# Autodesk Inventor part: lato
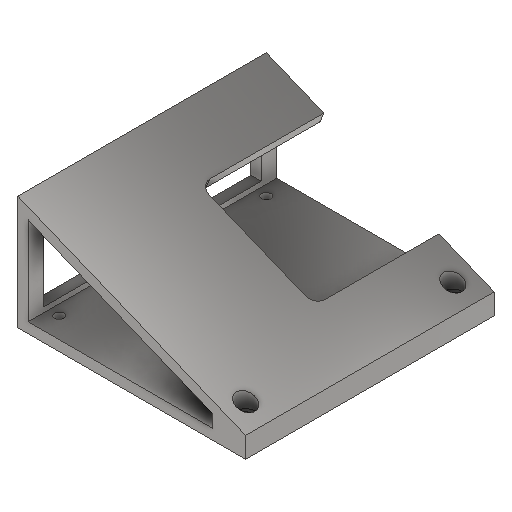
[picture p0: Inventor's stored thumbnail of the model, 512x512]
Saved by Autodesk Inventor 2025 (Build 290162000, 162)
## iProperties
Created: 2025-05
Part Number: lato
Material: Plastica PET
Document SubType Name: Modeling
Designer: R5800u
Density: 1.541 g/cm^3
Appearance: Acciaio - Lucido
Author: R5800u
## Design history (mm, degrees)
sketch "Schizzo1"
  geometry: L1 (0, 0)-(190, 0) reference; L2 (190, 0)-(190, 5) reference; L3 (0, 5)-(190, 5) reference; L4 (0, 0)-(0, 5) reference; L5 (300, -50)-(300, -55) reference; L6 (300, -50)-(300, -40); L7 (300, -40)-(190, 5); L8 (190, 5)-(190, -50); L9 (190, -50)-(300, -50); L10 (195, -2.448)-(295, -43.357); L11 (295, -43.357)-(295, -45); L12 (295, -45)-(195, -45); L13 (195, -45)-(195, -2.448); L14 (284, -38.857)-(284, -45); 1 further point
  constraints: 18 end point, 3 point on line, 2 perpendicular, 1 vertical, 3 other
  dimensions: "d0" = 10 distance of L5.start L6.end; "d1" = 5 distance between parallel lines of L7 L10; "d2" = 16 distance between parallel lines of L6 L14
extrude "Estrusione1" new body sketch "Schizzo1" distance "d3" = 120; taper "d4" = 0 deg
sketch "Schizzo2"
  geometry: L1 (0, 55)-(0, 0) reference; L2 (0, 55)-(-120, 55) reference; L3 (-120, 0)-(-120, 55) reference; L4 (0, 0)-(-120, 0) reference; L5 (-112.5, 47.5)-(-7.5, 47.5); L6 (-7.5, 47.5)-(-7.5, 7.5); L7 (-7.5, 7.5)-(-112.5, 7.5); L8 (-112.5, 7.5)-(-112.5, 47.5); 1 further point
  constraints: 8 end point, 3 other
  dimensions: "d5" = 7.5 distance between parallel lines of L2 L5
extrude "Estrusione2" cut sketch "Schizzo2" stored distance "d6" = 10; taper "d7" = 0 deg
sketch "Schizzo3"
  geometry: L1 (81.5, -69.5)-(81.5, -61.5) reference; L2 (93.5, -69.5)-(81.5, -69.5) reference; L3 (93.5, -61.5)-(93.5, -69.5) reference; L4 (81.5, -61.5)-(93.5, -61.5) reference; L5 (93.5, 61.5)-(81.5, 61.5) reference; L6 (81.5, 61.5)-(81.5, 69.5) reference; L7 (81.5, 69.5)-(93.5, 69.5) reference; 1 further point
  constraints: 14 end point, 4 horizontal, 3 vertical, 8 other
extrude "Estrusione3" cut sketch "Schizzo3" distance "d8" = 10; taper "d9" = 0 deg
sketch "Schizzo4"
  geometry: L1 (110, -107.9)-(110, -112.1) reference; L2 (110, -110)-(100, -110); L3 (0, -120)-(110, -120) reference; L4 (100, -120)-(100, 0); L5 (0, 0)-(110, 0) reference; L6 (100, -60)-(110, -60); L7 (110, 0)-(110, -120) reference; L8 (100, -10)-(10, -10); L9 (0, 0)-(0, -120) reference; 6 further points
  constraints: 10 end point, 3 midpoint, 3 point on line, 2 coincident, 2 horizontal, 2 symmetric about line, 2 vertical, 2 other
  dimensions: "d10" = 10 distance of L2.start L2.end; "d11" = 10 distance from line of L6 point (100, -70); "d19" = 10 distance from line of L9 L8.end
hole "Foro1" sketch "Schizzo4" at (100, -110), (100, -10), (10, -10), (10, -110) diameter "d12" = 4.5; stored, may be unused: countersink angle "d16" = 90 deg, drill point angle "d18" = 118 deg; dims "d13" = 6, "d14" = 9.4, "d15" = 2, "d17" = 20
node "Piano di lavoro1"
sketch "Schizzo6"
  geometry: C1 r 2.25 at (95, 110) reference; C2 r 2.25 at (95, 10) reference; 1 further point
hole "Foro2" sketch "Schizzo6" at (95, 10), (95, 110) diameter "d21" = 5.5; stored, may be unused: countersink angle "d25" = 90 deg, drill point angle "d27" = 118 deg; dims "d22" = 6, "d23" = 9, "d24" = 8, "d26" = 20
sketch "Schizzo7"
  geometry: L1 (3.786, 120)-(-98.024, 120) reference; L2 (-88.849, 120)-(-28.849, 120); L3 (-28.849, 120)-(-28.849, 60); L4 (-28.849, 60)-(-88.849, 60); L5 (-88.849, 60)-(-88.849, 120); L6 (-118.849, 0)-(-118.849, 120) reference; 2 further points
  constraints: 8 end point, 2 parallel, 1 horizontal, 1 perpendicular, 1 point on line
  dimensions: "d28" = 60 distance of L3.end L4.end; "d29" = 60 distance of L2.end L3.end; "d30" = 30 distance between parallel lines of L6 L5
extrude "Estrusione4" cut sketch "Schizzo7" distance "d31" = 10; taper "d32" = 0 deg
fillet "Raccordo1" dims "d33" = 5
node "Solido1"
node "Riferimento1"
node "Riferimento2"
node "Linea chiusa proiettata1"
other parameters: "d20" = 11
